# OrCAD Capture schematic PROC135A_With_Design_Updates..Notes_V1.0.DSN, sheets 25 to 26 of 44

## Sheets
25 25. TEST AUTOMATION: size C; title: TEST AUTOMATION
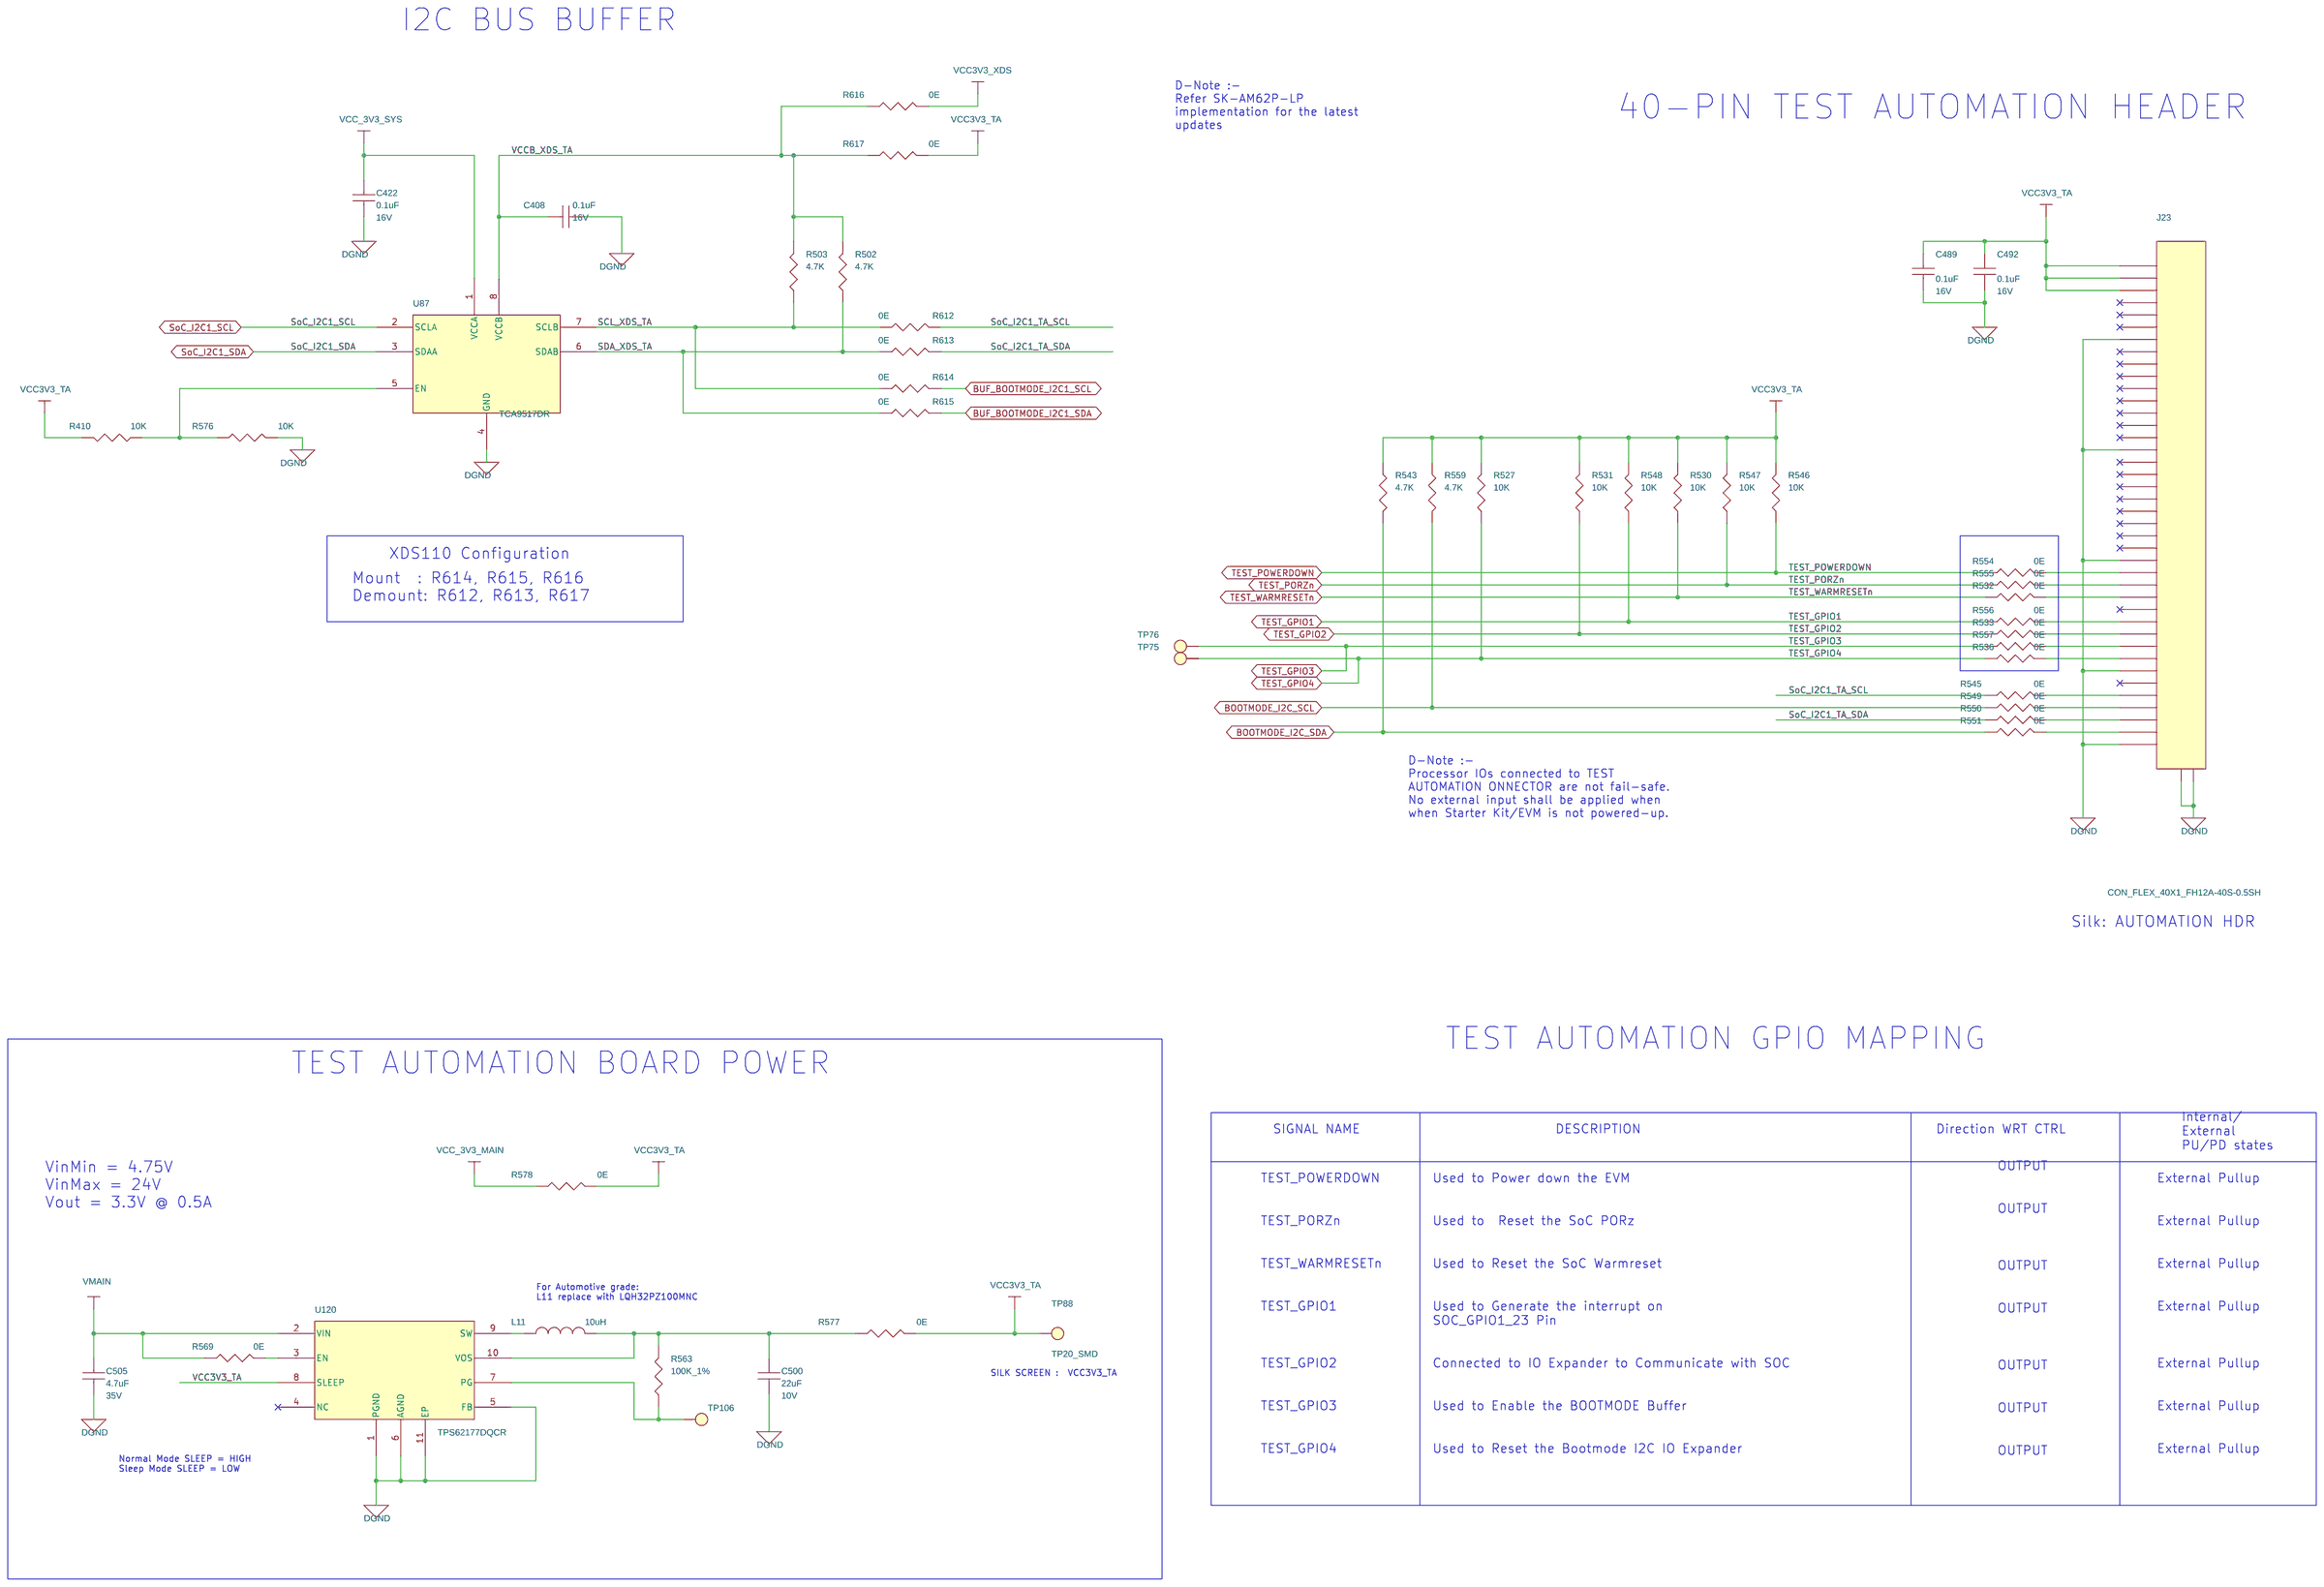
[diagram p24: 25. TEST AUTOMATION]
26 26. BOOT MODE BUFFER & SWITCHES: size C; title: BOOT MODE BUFFER & SWITCHES
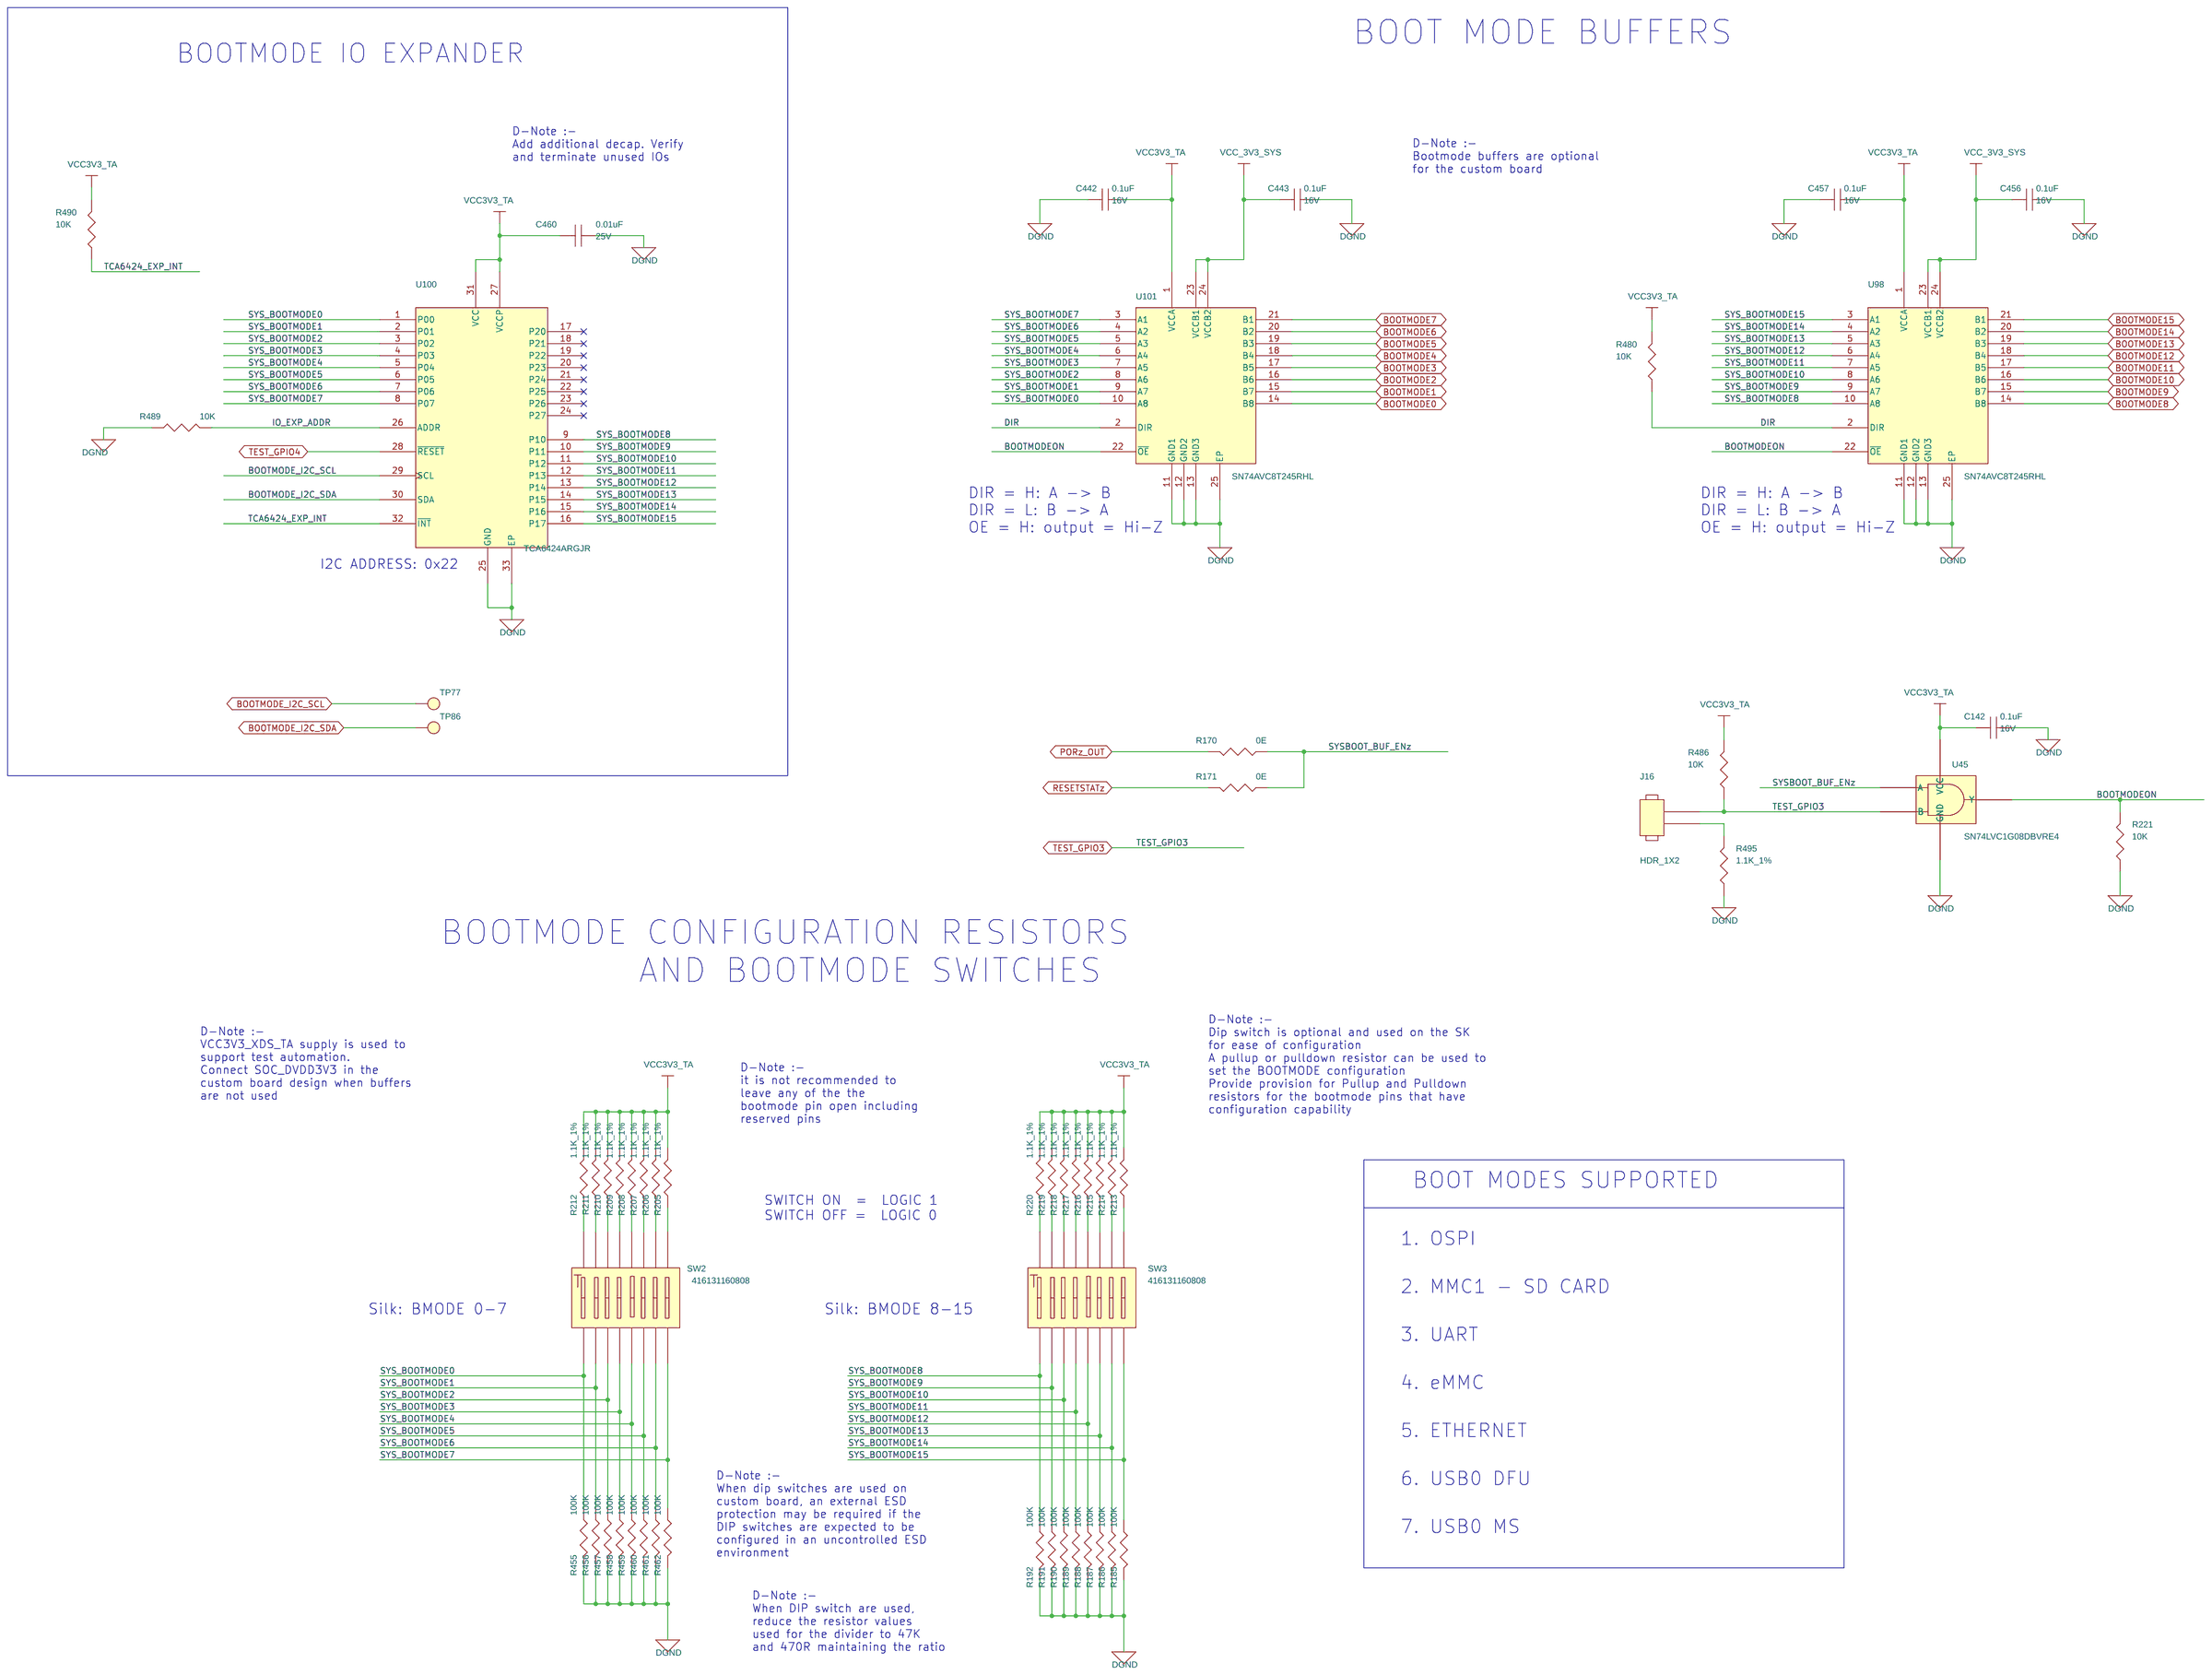
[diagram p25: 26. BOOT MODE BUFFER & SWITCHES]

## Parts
sheet 25. TEST AUTOMATION
C408  0.1uF  [CAP0201_0-5]
C422  0.1uF  [CAP0201_0-5]
C489  0.1uF  [CAP0201_0-5]
C492  0.1uF  [CAP0201_0-5]
C500  22uF  [CAP0603_1]
C505  4.7uF  [CAP0603_1]
J23  CON_FLEX_40X1_FH12A-40S-0.5SH  [CON_FLEX40X1_FH12A_S_R_S]
L11  10uH  [IND_1277AS-H_130X110_SMD_1-2]
R410  10K  [RES0201_0-5]
R502  4.7K  [RES0201_0-5]
R503  4.7K  [RES0201_0-5]
R527  10K  [RES0201_0-5]
R530  10K  [RES0201_0-5]
R531  10K  [RES0201_0-5]
R532  0E  [RES0201_0-5]
R533  0E  [RES0201_0-5]
R536  0E  [RES0201_0-5]
R543  4.7K  [RES0201_0-5]
R545  0E  [RES0201_0-5]
R546  10K  [RES0201_0-5]
R547  10K  [RES0201_0-5]
R548  10K  [RES0201_0-5]
R549  0E  [RES0201_0-5]
R550  0E  [RES0201_0-5]
R551  0E  [RES0201_0-5]
R554  0E  [RES0201_0-5]
R555  0E  [RES0201_0-5]
R556  0E  [RES0201_0-5]
R557  0E  [RES0201_0-5]
R559  4.7K  [RES0201_0-5]
R563  100K_1%  [RES0402_0-5]
R569  0E  [RES0402_0-5]
R576  10K  [RES0201_0-5]
R577  0E  [RES0805_0-75]
R578  0E  [RES0805_0-75]
R612  0E  [RES0201_0-5]
R613  0E  [RES0201_0-5]
R614  0E  [RES0201_0-5]
R615  0E  [RES0201_0-5]
R616  0E  [RES0402_0-5]
R617  0E  [RES0402_0-5]
TP75  TP20_SMD  [TP20_SMD]
TP76  TP20_SMD  [TP20_SMD]
TP88  TP20_SMD  [TP20_SMD]
TP106  TP20_SMD  [TP20_SMD]
U87  TCA9517DR  [SOIC8_1-8]
U120  TPS62177DQCR  [WSON10_19-68_80X120_0-8]
sheet 26. BOOT MODE BUFFER & SWITCHES
C142  0.1uF  [CAP0201_0-5]
C442  0.1uF  [CAP0201_0-5]
C443  0.1uF  [CAP0201_0-5]
C456  0.1uF  [CAP0201_0-5]
C457  0.1uF  [CAP0201_0-5]
C460  0.01uF  [CAP0201_0-5]
J16  HDR_1X2  [HDR_1X2_90120-0122_S_T_5-6]
R170  0E  [RES0201_0-5]
R171  0E  [RES0201_0-5]
R185  100K  [RES0201_0-5]
R186  100K  [RES0201_0-5]
R187  100K  [RES0201_0-5]
R188  100K  [RES0201_0-5]
R189  100K  [RES0201_0-5]
R190  100K  [RES0201_0-5]
R191  100K  [RES0201_0-5]
R192  100K  [RES0201_0-5]
R205  1.1K_1%  [RES0201_0-5]
R206  1.1K_1%  [RES0201_0-5]
R207  1.1K_1%  [RES0201_0-5]
R208  1.1K_1%  [RES0201_0-5]
R209  1.1K_1%  [RES0201_0-5]
R210  1.1K_1%  [RES0201_0-5]
R211  1.1K_1%  [RES0201_0-5]
R212  1.1K_1%  [RES0201_0-5]
R213  1.1K_1%  [RES0201_0-5]
R214  1.1K_1%  [RES0201_0-5]
R215  1.1K_1%  [RES0201_0-5]
R216  1.1K_1%  [RES0201_0-5]
R217  1.1K_1%  [RES0201_0-5]
R218  1.1K_1%  [RES0201_0-5]
R219  1.1K_1%  [RES0201_0-5]
R220  1.1K_1%  [RES0201_0-5]
R221  10K  [RES0201_0-5]
R455  100K  [RES0201_0-5]
R456  100K  [RES0201_0-5]
R457  100K  [RES0201_0-5]
R458  100K  [RES0201_0-5]
R459  100K  [RES0201_0-5]
R460  100K  [RES0201_0-5]
R461  100K  [RES0201_0-5]
R462  100K  [RES0201_0-5]
R480  10K  [RES0201_0-5]
R486  10K  [RES0201_0-5]
R489  10K  [RES0201_0-5]
R490  10K  [RES0201_0-5]
R495  1.1K_1%  [RES0201_0-5]
SW2  416131160808  [SW16_416131160808_460X230_SMD_2-7]
SW3  416131160808  [SW16_416131160808_460X230_SMD_2-7]
TP77  TP20_SMD  [TP20_SMD]
TP86  TP20_SMD  [TP20_SMD]
U45  SN74LVC1G08DBVRE4  [SOT23-5]
U98  SN74AVC8T245RHL  [QFN24_19-68_220X140_1]
U100  TCA6424ARGJR  [QFN32_19-68_200X200]
U101  SN74AVC8T245RHL  [QFN24_19-68_220X140_1]

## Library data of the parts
C142 C408 C422 C442 C443 C456 C457 C489 C492 = CAP: CAP CERAMIC 0.1uF 16V 10% X5R 0201; Alt_Mfr_name: YAGEO AMERICA; Alt_Mfr_part_number: CC0402KRX5R8BB104; Chkd/date: MANIRAJA/230118; Crtd /date: MANIRAJA/230118; Custom_Duty: 15%; Customs_HS_Code: 85322990; Distributor_name: DIGIKEY; Distributor_part_number: 490-14305-1-ND; Footprint Path: Y:\MIS_DATABASE\Library\ALTIUM_TOOL\PCB_FOOTPRINTS\Altium_Footprint_Lib.PcbLib; Height: 0.33MM; Library Path: Y:\MIS_DATABASE\Library\ALTIUM_TOOL\SCHEMATICS_PARTS\MS_DISCRETE_Library.schlib; Mfr_name: MURATA; Mfr_part_number: GRM033R61C104KE14D; Mistral Part No: 120009030072-R; Package: 0201; Part_type: CAPACITORS\CERAMIC; Project: TI_MAXIE_CPB; RoHS: RoHS; Temperature: -55°C+85°C; Tolerance: 10%; Voltage: 16V; Wattage: NA; Weight: 0.33mg; Datasheet: Y:\MIS_DATABASE\DATASHEETS\CAPACITORS\GRM033R61C104KE14.PDF
C500 = CAP: CAP CERAMIC 22uF 10V 20% X5R 0603; Chkd/date: MANIRAJA/230118; Crtd /date: MANIRAJA/230118; Custom_Duty: 15%; Customs_HS_Code: 85322990; Distributor_name: DIGIKEY; Distributor_part_number: 490-10476-1-ND; Footprint Path: Y:\MIS_DATABASE\Library\ALTIUM_TOOL\PCB_FOOTPRINTS\Altium_Footprint_Lib.PcbLib; Height: 1.00MM; Library Path: Y:\MIS_DATABASE\Library\ALTIUM_TOOL\SCHEMATICS_PARTS\MS_DISCRETE_Library.schlib; Mfr_name: MURATA; Mfr_part_number: GRM188R61A226ME15D; Mistral Part No: 120014100009-R; Package: 0603; Part_type: CAPACITORS\CERAMIC; Project: TI_MAXIE_CPB; RoHS: RoHS; Temperature: -55°C+85°C; Tolerance: 20%; Voltage: 10V; Wattage: NA; Weight: 6.3mg; Datasheet: Y:\MIS_DATABASE\DATASHEETS\CAPACITORS\GRM188R61A226ME15.PDF
C505 = CAP: CAP CERAMIC 4.7uF 35V 20% X5R 0603; Chkd/date: MANIRAJA/120520; Crtd /date: ALVY/120520; Custom_Duty: 15%; Customs_HS_Code: 85322990; Distributor_name: DIGIKEY; Distributor_part_number: 490-11995-1-ND; Footprint Path: Y:\MIS_DATABASE\Library\ALTIUM_TOOL\PCB_FOOTPRINTS\Altium_Footprint_Lib.PcbLib; Height: 1.00MM; Library Path: Y:\MIS_DATABASE\Library\ALTIUM_TOOL\SCHEMATICS_PARTS\MS_DISCRETE_Library.schlib; Mfr_name: MURATA; Mfr_part_number: GRM188R6YA475ME15D; Mistral Part No: 120020050017-R; Package: 0603; Part_type: CAPACITORS\CERAMIC; Project: SD865_NANOSOM; RoHS: RoHS; Temperature: -55°C+85°C; Tolerance: 20%; Voltage: 35V; Wattage: NA; Weight: 6.3mg; Datasheet: Y:\MIS_DATABASE\DATASHEETS\CAPACITORS\GRM188R6YA475ME15.PDF
J23 = CON_FLEX_40X1_FH12A-40S-0.5SH: CON FPC 40X1 0.50MM PITCH RT TOP SMD; Chkd/date: SHREESHAIL/201106; Crtd /date: MAZHAR/171106; Custom_Duty: 24%; Customs_HS_Code: 85369090; Distributor_name: DIGIKEY; Distributor_part_number: HFK40CT-ND; Height: 2.00MM; Mfr_name: HIROSE ELECTRIC EUROPE; Mfr_part_number: FH12A-40S-0.5SH(55); Mistral Part No: 150009030176-R; Package: SMD; Part_type: CONNECTOR\FPC; Project: PMP LCD BOARD; Datasheet: Y:\MIS_DATABASE\DATASHEETS\CONNECTORS\FH12SERIES.PDF
L11 = INDUCTOR: IND POWER 10uH 900mA 20% SMD; Chkd/date: MANIRAJA/200921; Crtd /date: ALVY/200921; Custom_Duty: 24%; Customs_HS_Code: 85369090; Distributor_name: DIGIKEY; Distributor_part_number: 490-10589-1-ND; Footprint Path: Y:\MIS_DATABASE\Library\ALTIUM_TOOL\PCB_FOOTPRINTS\Altium_Footprint_Lib.PcbLib; Height: 1.20MM; Library Path: Y:\MIS_DATABASE\Library\ALTIUM_TOOL\SCHEMATICS_PARTS\MS_DISCRETE_Library.schlib; Mfr_name: MURATA; Mfr_part_number: 1277AS-H-100M=P2; Mistral Part No: 130021090022-R; Package: SMD; Project: TI_AM62x SKEVM_BRD; RoHS: RoHS; Temperature: -40°C+85°C; Tolerance: 20%; Voltage: NA; Wattage: NA; Weight: NA; Datasheet: Y:\MIS_DATABASE\DATASHEETS\DISCRETES\INDUCTORS\MURATA-1277AS-H.PDF
R221 R410 R480 R486 R489 R490 R527 R530 R531 R546-R548 R576 = RESISTOR: RES 10K 1/20W 5% 0201; Chkd/date: MANIRAJA/050517; Crtd /date: MANIRAJA/050517; Custom_Duty: 15%; Customs_HS_Code: 85332119; Distributor_name: DIGIKEY; Distributor_part_number: 311-10KNCT-ND; Footprint Path: Y:\MIS_DATABASE\Library\ALTIUM_TOOL\PCB_FOOTPRINTS\Altium_Footprint_Lib.PcbLib; Height: 0.26MM; Library Path: Y:\MIS_DATABASE\Library\ALTIUM_TOOL\SCHEMATICS_PARTS\MS_DISCRETE_Library.schlib; Mfr_name: YAGEO AMERICA; Mfr_part_number: RC0201JR-0710KL; Mistral Part No: 110010070051-R; Package: 0201; Part_type: RESISTORS\FIXED; Project: GOLDEN-I LITE; RoHS: RoHS; Temperature: -55°C+125°C; Tolerance: 5%; Voltage: NA; Wattage: 1/20W; Weight: 0.17mg; Datasheet: Y:\MIS_DATABASE\DATASHEETS\RESISTORS\RCXXXXL-SER_MAR18.PDF
R502 R503 R543 R559 = RESISTOR: RES 4.7K 1/20W 5% 0201; Chkd/date: MANIRAJA/200921; Crtd /date: ALVY/200921; Custom_Duty: 15%; Customs_HS_Code: 85332119; Distributor_name: DIGIKEY; Distributor_part_number: 311-4.7KNCT-ND; Footprint Path: Y:\MIS_DATABASE\Library\ALTIUM_TOOL\PCB_FOOTPRINTS\Altium_Footprint_Lib.PcbLib; Height: 0.26MM; Library Path: Y:\MIS_DATABASE\Library\ALTIUM_TOOL\SCHEMATICS_PARTS\MS_DISCRETE_Library.schlib; Mfr_name: YAGEO AMERICA; Mfr_part_number: RC0201JR-074K7L; Mistral Part No: 110021090007-R; Package: 0201; Part_type: RESISTORS\FIXED; Project: TI_AM62x SKEVM_BRD; RoHS: RoHS; Temperature: -55°C+125°C; Tolerance: 5%; Voltage: NA; Wattage: 1/20W; Weight: 0.17mg; Datasheet: Y:\MIS_DATABASE\DATASHEETS\RESISTORS\RCXXXXL-SER_MAR18.PDF
R170 R171 R532 R533 R536 R545 R549-R551 R554-R557 R612-R615 = RESISTOR: RES 0E 1/20W 5% 0201; Chkd/date: NAVEED/301214; Crtd /date: MUDDU/120710; Custom_Duty: 15%; Customs_HS_Code: 85332119; Distributor_name: DIGIKEY; Distributor_part_number: 311-0.0NCT-ND; Footprint Path: Y:\MIS_DATABASE\Library\ALTIUM_TOOL\PCB_FOOTPRINTS\Altium_Footprint_Lib.PcbLib; Height: 0.26MM; Library Path: Y:\MIS_DATABASE\Library\ALTIUM_TOOL\SCHEMATICS_PARTS\MS_DISCRETE_Library.schlib; Mfr_name: YAGEO AMERICA; Mfr_part_number: RC0201JR-070RL; Mistral Part No: 110010070067-R; Package: 0201; Part_type: RESISTORS\FIXED; Project: PB_BUGBASE; RoHS: RoHS; Temperature: -55°C+125°C; Tolerance: 5%; Voltage: NA; Wattage: 1/20W; Weight: 0.17mg; Datasheet: Y:\MIS_DATABASE\DATASHEETS\RESISTORS\RCXXXXL-SER_MAR18.PDF
R563 = RESISTOR: RES 100K 1/10W 1% 0402; Chkd/date: VASANTHA/201216; Crtd /date: MAZHAR/130306; Custom_Duty: 15%; Customs_HS_Code: 85332119; Distributor_name: DIGIKEY; Distributor_part_number: P100KLCT-ND; Footprint Path: Y:\MIS_DATABASE\Library\ALTIUM_TOOL\PCB_FOOTPRINTS\Altium_Footprint_Lib.PcbLib; Height: 0.40MM; Library Path: Y:\MIS_DATABASE\Library\ALTIUM_TOOL\SCHEMATICS_PARTS\MS_DISCRETE_Library.schlib; Mfr_name: PANASONIC-ECG; Mfr_part_number: ERJ-2RKF1003X; Mistral Part No: 110009030187-R; Package: 0402; Part_type: RESISTORS\FIXED; Project: J32; RoHS: RoHS; Temperature: -55°C+155°C; Tolerance: 1%; Voltage: NA; Wattage: 1/10W; Weight: 0.8mg; Datasheet: Y:\MIS_DATABASE\DATASHEETS\RESISTORS\PAN-ERJSER_NOV17.PDF
R569 = RESISTOR: RES 0E 1/16W JUMPER 0402; Chkd/date: VASANTHA/201216; Crtd /date: MUDDU/190810; Custom_Duty: 15%; Customs_HS_Code: 85332119; Distributor_name: DIGIKEY; Distributor_part_number: 541-0.0JCT-ND; Footprint Path: Y:\MIS_DATABASE\Library\ALTIUM_TOOL\PCB_FOOTPRINTS\Altium_Footprint_Lib.PcbLib; Height: 0.40MM; Library Path: Y:\MIS_DATABASE\Library\ALTIUM_TOOL\SCHEMATICS_PARTS\MS_DISCRETE_Library.schlib; Mfr_name: VISHAY; Mfr_part_number: CRCW04020000Z0ED; Mistral Part No: 110010080019-R; Package: 0402; Part_type: RESISTORS\FIXED; Project: PB_BUGBASE; RoHS: RoHS; Temperature: -55°C+155°C; Tolerance: NA; Voltage: NA; Wattage: 1/16W; Weight: 0.65mg; Datasheet: Y:\MIS_DATABASE\DATASHEETS\RESISTORS\CRCW0603.PDF
R577 R578 = RESISTOR: RES 0E 1/8W 5% 0805; Chkd/date: VASANTHA/130416; Crtd /date: JEBRAN/020316; Custom_Duty: 15%; Customs_HS_Code: 85332119; Distributor_name: DIGIKEY; Distributor_part_number: 311-0.0ARCT-ND; Footprint Path: Y:\MIS_DATABASE\Library\ALTIUM_TOOL\PCB_FOOTPRINTS\Altium_Footprint_Lib.PcbLib; Height: 0.60MM; Library Path: Y:\MIS_DATABASE\Library\ALTIUM_TOOL\SCHEMATICS_PARTS\MS_DISCRETE_Library.schlib; Mfr_name: YAGEO AMERICA; Mfr_part_number: RC0805JR-070RL; Mistral Part No: 110009030074-R; Package: 0805; Part_type: RESISTORS\FIXED; Project: ZK_BIOMETRIC; RoHS: RoHS; Temperature: -55°C+155°C; Tolerance: 5%; Voltage: NA; Wattage: 1/8W; Weight: 5.5mg; Datasheet: Y:\MIS_DATABASE\DATASHEETS\RESISTORS\RCXXXXL-SER_MAR18.PDF
R616 R617 = RESISTOR: RES 0E 1/10W JUMPER 0402; Chkd/date: VASANTHA/061216; Crtd /date: NAVEED/201014; Custom_Duty: 15%; Customs_HS_Code: 85332119; Distributor_name: DIGIKEY; Distributor_part_number: P0.0JCT-ND; Footprint Path: Y:\MIS_DATABASE\Library\ALTIUM_TOOL\PCB_FOOTPRINTS\Altium_Footprint_Lib.PcbLib; Height: 0.40MM; IBISSP_MODLES: VALUE REPEATING 2 TIME; Library Path: Y:\MIS_DATABASE\Library\ALTIUM_TOOL\SCHEMATICS_PARTS\MS_DISCRETE_Library.schlib; Mfr_name: PANASONIC-ECG; Mfr_part_number: ERJ-2GE0R00X; Mistral Part No: 110018030052-R; Package: 0402; Part_type: RESISTORS\FIXED; Project: AEGIS POM; RoHS: RoHS; Temperature: -55°C+155°C; Tolerance: NA; Voltage: NA; Wattage: 1/10W; Weight: 0.8mg; Datasheet: Y:\MIS_DATABASE\DATASHEETS\RESISTORS\PAN-ERJSER_NOV17.PDF
TP75-TP77 TP86 TP106 = TESTPOINT: TESTPOINT CIR 20 SMD; Chkd/date: SHREESHAIL/171006; Crtd /date: MAZHAR/171006; Custom_Duty: NA; Customs_HS_Code: NA; Distributor_name: NA; Distributor_part_number: NA; Footprint Path: Y:\MIS_DATABASE\Library\ALTIUM_TOOL\PCB_FOOTPRINTS\Altium_Footprint_Lib.PcbLib; Height: NA; Library Path: Y:\MIS_DATABASE\Library\ALTIUM_TOOL\SCHEMATICS_PARTS\MS_DISCRETE_Library.schlib; MECHANICAL 3D STEP FILE: NA; Mfr_name: LOCAL; Mistral Part No: NA; Package: SMD; Project: BT MODULE_CSRBC04; RoHS: NA; Temperature: NA; Tolerance: NA; Voltage: NA; Wattage: NA; Weight: NA; Datasheet: NA
TP88 = TESTPOINT: TESTPOINT CIR 20 SMD; Chkd/date: SHREESHAIL/171006; Crtd /date: MAZHAR/171006; Custom_Duty: NA; Customs_HS_Code: NA; Distributor_name: NA; Distributor_part_number: NA; Footprint Path: Y:\MIS_DATABASE\Library\ALTIUM_TOOL\PCB_FOOTPRINTS\Altium_Footprint_Lib.PcbLib; Height: NA; Library Path: Y:\MIS_DATABASE\Library\ALTIUM_TOOL\SCHEMATICS_PARTS\MS_DISCRETE_Library.schlib; MECHANICAL 3D STEP FILE: NA; Manufacturer: LOCAL; Mfr_name: LOCAL; Mistral Part No: NA; Package: SMD; Project: BT MODULE_CSRBC04; RoHS: NA; Temperature: NA; Tolerance: NA; Voltage: NA; Wattage: NA; Weight: NA; Datasheet: NA
U87 = TCA9517DGKR_VSSOP8: IC 2-CHANNEL BI-DIR LEVEL-SHIFTING I2C BUS REPEATER SOIC8; Chkd/date: MANIRAJA/171121; Crtd /date: ALVY/161121; Custom_Duty: 15%; Customs_HS_Code: 85423100; Distributor_name: DIGIKEY; Distributor_part_number: 296-39221-1-ND; Footprint Path: Y:\MIS_DATABASE\Library\ALTIUM_TOOL\PCB_FOOTPRINTS\Altium_Footprint_Lib.PcbLib; Height: 1.75MM; Library Path: Y:\MIS_DATABASE\Library\ALTIUM_TOOL\SCHEMATICS_PARTS\MS_MISCINTERFACE_Library.schlib; Mfr_name: TEXAS INSTRUMENTS; Mistral Part No: 141021110017-R; Package: SOIC8; Part_type: ICS\INTERFACE\LEVEL TRANSLATOR; Project: EXCITER MULTI-CH RX UNIT; RoHS: RoHS; Temperature: -40°C+85°C; Tolerance: NA; Voltage: NA; Wattage: NA; Weight: 540mg; Datasheet: Y:\MIS_DATABASE\DATASHEETS\ICS\INTERFACE\TCA9517.PDF
U120 = TPS62177_WSON10: IC 3.3V 0.5A STEP DOWN CONVERTER WITH SLEEP MODE WSON10; Chkd/date: MANIRAJA/170719; Crtd /date: MANIRAJA/170719; Custom_Duty: 15%; Customs_HS_Code: 85423100; Distributor_name: DIGIKEY; Distributor_part_number: 296-41856-1-ND; Footprint Path: Y:\MIS_DATABASE\Library\ALTIUM_TOOL\PCB_FOOTPRINTS\Altium_Footprint_Lib.PcbLib; Height: 0.80MM; Library Path: Y:\MIS_DATABASE\Library\ALTIUM_TOOL\SCHEMATICS_PARTS\MS_MISCPOWER_Library.schlib; Mfr_name: TEXAS INSTRUMENTS; Mistral Part No: 142019070007-R; Package: WSON10; Part_type: ICS\POWER\DC-DC CONVERTER; Project: TI_MAXIE_CPB; RoHS: RoHS; Temperature: -40°C+85°C; Tolerance: NA; Voltage: NA; Wattage: NA; Weight: 15mg; Datasheet: Y:\MIS_DATABASE\DATASHEETS\ICS\POWER\TPS62177.PDF
C460 = CAP: CAP CERAMIC 0.01uF 25V 10% X5R 0201; Chkd/date: MANIRAJA/230118; Crtd /date: MANIRAJA/230118; Custom_Duty: 15%; Customs_HS_Code: 85322990; Distributor_name: DIGIKEY; Distributor_part_number: GRM033R61E103KA12J-ND; Footprint Path: Y:\MIS_DATABASE\Library\ALTIUM_TOOL\PCB_FOOTPRINTS\Altium_Footprint_Lib.PcbLib; Height: 0.33MM; Library Path: Y:\MIS_DATABASE\Library\ALTIUM_TOOL\SCHEMATICS_PARTS\MS_DISCRETE_Library.schlib; Mfr_name: MURATA; Mfr_part_number: GRM033R61E103KA12J; Mistral Part No: 120018010007-R; Package: 0201; Part_type: CAPACITORS\CERAMIC; Project: TI_MAXIE_CPB; RoHS: RoHS; Temperature: -55°C+85°C; Tolerance: 10%; Voltage: 25V; Wattage: NA; Weight: 0.33mg; Datasheet: Y:\MIS_DATABASE\DATASHEETS\CAPACITORS\GRM033R61E103KA12.PDF
J16 = HEADER_2X1: CON HDR 1X2 2.54MM PITCH ST TH; Chkd/date: NAVEED/210714; Crtd /date: USMAN/031012; Custom_Duty: 24%; Customs_HS_Code: 85369090; Distributor_name: DIGIKEY; Distributor_part_number: WM8072-ND; Footprint Path: Y:\MIS_DATABASE\Library\ALTIUM_TOOL\PCB_FOOTPRINTS\Altium_Footprint_Lib.PcbLib; Height: 5.60MM; Library Path: Y:\MIS_DATABASE\Library\ALTIUM_TOOL\SCHEMATICS_PARTS\MS_CONNECTOR_Library.schlib; Mfr_name: MOLEX; Mfr_part_number: 90120-0122; Mistral Part No: 150012100005-R; Package: THRU-HOLE; Part_type: CONNECTOR\HEADERS; Project: NPOL_FEP; RoHS: RoHS; Temperature: -55°C+125°C; Tolerance: NA; Voltage: NA; Wattage: NA; Weight: 122mg; Datasheet: Y:\MIS_DATABASE\DATASHEETS\CONNECTORS\90120-XX.PDF
R185-R192 R455-R462 = RESISTOR: RES 100K 1/20W 5% 0201; Chkd/date: MANIRAJA/050517; Crtd /date: MANIRAJA/050517; Custom_Duty: 15%; Customs_HS_Code: 85332119; Distributor_name: DIGIKEY; Distributor_part_number: 311-100KNCT-ND; Footprint Path: Y:\MIS_DATABASE\Library\ALTIUM_TOOL\PCB_FOOTPRINTS\Altium_Footprint_Lib.PcbLib; Height: 0.26MM; Library Path: Y:\MIS_DATABASE\Library\ALTIUM_TOOL\SCHEMATICS_PARTS\MS_DISCRETE_Library.schlib; Mfr_name: YAGEO AMERICA; Mfr_part_number: RC0201JR-07100KL; Mistral Part No: 110009030176-R; Package: 0201; Part_type: RESISTORS\FIXED; Project: GOLDEN-I LITE; RoHS: RoHS; Temperature: -55°C+125°C; Tolerance: 5%; Voltage: NA; Wattage: 1/20W; Weight: 0.17mg; Datasheet: Y:\MIS_DATABASE\DATASHEETS\RESISTORS\RCXXXXL-SER_MAR18.PDF
R205-R220 R495 = RESISTOR: RES 1.1K 1/20W 1% 0201; Chkd/date: MANIRAJA/270721; Crtd /date: ALVY/260721; Custom_Duty: 15%; Customs_HS_Code: 85332119; Distributor_name: DIGIKEY; Distributor_part_number: YAG2474CT-ND; Footprint Path: Y:\MIS_DATABASE\Library\ALTIUM_TOOL\PCB_FOOTPRINTS\Altium_Footprint_Lib.PcbLib; Height: 0.26MM; Library Path: Y:\MIS_DATABASE\Library\ALTIUM_TOOL\SCHEMATICS_PARTS\MS_DISCRETE_Library.schlib; Mfr_name: YAGEO AMERICA; Mfr_part_number: RC0201FR-071K1L; Mistral Part No: 110009030097-R; Package: 0201; Part_type: RESISTORS\FIXED; Project: TI_AM335x SK_BRD; RoHS: RoHS; Temperature: -55°C+125°C; Tolerance: 1%; Voltage: NA; Wattage: 1/20W; Weight: 0.17mg; Datasheet: Y:\MIS_DATABASE\DATASHEETS\RESISTORS\RCXXXXL-SER_MAR18.PDF
SW2 SW3 = SW16_CHS-08A: SWITCH SLIDE SPST ST SMD; Chkd/date: MANIRAJA/051020; Crtd /date: ALVY/011020; Custom_Duty: 24%; Customs_HS_Code: 85369090; Distributor_name: DIGIKEY; Distributor_part_number: 732-3857-1-ND; Footprint Path: Y:\MIS_DATABASE\Library\ALTIUM_TOOL\PCB_FOOTPRINTS\Altium_Footprint_Lib.PcbLib; Height: 2.65MM; Library Path: Y:\MIS_DATABASE\Library\ALTIUM_TOOL\SCHEMATICS_PARTS\MS_SWITCH_Library.schlib; Mfr_name: WURTH ELECTRONICS; Mistral Part No: 130020100001-R; Package: SMD; Part_type: ELECTRO-MECHANICAL\SWITCH; Project: AM64X_SKEVM; RoHS: RoHS; Temperature: -40°C+85°C; Tolerance: NA; Voltage: NA; Wattage: NA; Weight: 281.7mg; Datasheet: Y:\MIS_DATABASE\DATASHEETS\MISC\SWITCHES\4161311608XX.PDF
U45 = SN74LVC1G08DBVRE4_SOT23-5: IC SINGLE 2-INPUT POSITIVE AND GATE SOT23-5; Chkd/date: SUHAS/221010; Crtd /date: USMAN/151008; Custom_Duty: 15%; Customs_HS_Code: 85423100; Distributor_name: DIGIKEY; Distributor_part_number: SN74LVC1G08DBVRE4-ND; Height: 1.45MM; Mfr_name: TEXAS INSTRUMENTS; Mistral Part No: 141009060026-R; Part_type: ICS\DIGITAL\GATES; Project: KHAN_MAIN; RoHS: Sb/ Br FREE; Temperature: -40°C+85°C; Datasheet: Y:\MIS_DATABASE\DATASHEETS\ICS\DIGITAL\GATES\SN74LVC1G08.PDF
U98 U101 = SN74AVC8T245RHL_QFN24: IC BUS TRANSCEIVER 8-BIT DUAL-SUPPLY QFN24; Chkd/date: VASANTHA/231216; Crtd /date: BAVISH/290411; Custom_Duty: 15%; Customs_HS_Code: 85423100; Distributor_name: DIGIKEY; Distributor_part_number: 296-17859-1-ND; Height: 1.00MM; Mfr_name: TEXAS INSTRUMENTS; Mfr_part_number: SN74AVC8T245RHLR; Mistral Part No: 143011040001-R; Package: QFN24; Part_type: ICS\TELECOM\TRANSCEIVER; Project: OMAPL1_PEC20; RoHS: RoHS; Temperature: -40°C+85°C; Tolerance: NA; Voltage: NA; Wattage: NA; Weight: NA; Datasheet: Y:\MIS_DATABASE\DATASHEETS\ICS\DIGITAL\BUSTRANSCEIVER\SN74AVC8T245.PDF
U100 = TCA6424ARGJR_QFN32: IC I2C I/O EXPANDER 24B UQFN32; Chkd/date: NAVEED/100715; Crtd /date: NAVEED/100914; Custom_Duty: 15%; Customs_HS_Code: 85423100; Distributor_name: DIGIKEY; Distributor_part_number: 296-27844-1-ND; Height: 0.60MM; Mfr_name: TEXAS INSTRUMENTS; Mistral Part No: 141014090009-R; Package: UQFN32; Part_type: ICS\DIGITAL\BUSTRANSCEIVER; Project: ZK_BIOMETRIC; RoHS: RoHS; Temperature: -40°C+85°C; Weight: NA; Datasheet: Y:\MIS_DATABASE\DATASHEETS\ICS\DIGITAL\BUSTRANSCEIVER\TCA6424AR.PDF

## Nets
DGND: C142.2 C408.2 C422.2 C442.1 C443.2 C456.2 C457.1 C460.1 C489.2 C492.2 C500.2 C505.2 J23.7 J23.16 J23.25 J23.34 J23.40 J23.41 J23.42 R185.2 R186.2 R187.2 R188.2 R189.2 R190.2 R191.2 R192.2 R221.1 R455.2 R456.2 R457.2 R458.2 R459.2 R460.2 R461.2 R462.2 R489.2 R495.1 R576.1 U45.3(GND) U87.4(GND) U98.11(GND1) U98.12(GND2) U98.13(GND3) U98.25(EP) U100.25(GND) U100.33(EP) U101.11(GND1) U101.12(GND2) U101.13(GND3) U101.25(EP) U120.1(PGND) U120.5(FB) U120.6(AGND) U120.11(EP) ; also on sheet 9 10 11 12 13 14 15 16 17 18 19 20 21 22 23 24 27 28 29 30 31 32 33 34 35 36 37 38 39 40 41 42 43
VCC3V3_TA: C142.1 C442.2 C457.2 C460.2 C489.1 C492.1 J23.1 J23.2 J23.3 R205.2 R206.2 R207.2 R208.2 R209.2 R210.2 R211.2 R212.2 R213.2 R214.2 R215.2 R216.2 R217.2 R218.2 R219.2 R220.2 R410.1 R480.2 R486.2 R490.2 R527.2 R530.2 R531.2 R543.1 R546.2 R547.2 R548.2 R559.1 R577.2 R578.2 R617.2 TP88.1(TP) U45.5(VCC) U98.1(VCCA) U100.27(VCCP) U100.31(VCC) U101.1(VCCA) U120.8(SLEEP) ; also on sheet 27
VCC3V3_XDS: R616.2 ; also on sheet 27 28
VCC_3V3_MAIN: R578.1 ; also on sheet 11 12 14
VCC_3V3_SYS: C422.1 C443.1 C456.1 U87.1(VCCA) U98.23(VCCB1) U98.24(VCCB2) U101.23(VCCB1) U101.24(VCCB2) ; also on sheet 9 10 12 13 17 18 19 21 22 23 28 29 30 32 33 34 35 36 37 38 39 40 41 42
VCCB_XDS_TA: C408.1 R502.1 R503.1 R616.1 R617.1 U87.8(VCCB)
BOOTMODE0: U101.14(B8) ; also on sheet 31
BOOTMODE1: U101.15(B7) ; also on sheet 31
BOOTMODE2: U101.16(B6) ; also on sheet 31
BOOTMODE3: U101.17(B5) ; also on sheet 31
BOOTMODE4: U101.18(B4) ; also on sheet 31
BOOTMODE5: U101.19(B3) ; also on sheet 31
BOOTMODE6: U101.20(B2) ; also on sheet 31
BOOTMODE7: U101.21(B1) ; also on sheet 31
BOOTMODE8: U98.14(B8) ; also on sheet 31
BOOTMODE9: U98.15(B7) ; also on sheet 31
BOOTMODE10: U98.16(B6) ; also on sheet 31
BOOTMODE11: U98.17(B5) ; also on sheet 31
BOOTMODE12: U98.18(B4) ; also on sheet 31
BOOTMODE13: U98.19(B3) ; also on sheet 31
BOOTMODE14: U98.20(B2) ; also on sheet 31
BOOTMODE15: U98.21(B1) ; also on sheet 31
BOOTMODE_I2C_SCL: R549.1 R559.2 TP77.1(TP) U100.29(SCL) ; also on sheet 27
BOOTMODE_I2C_SDA: R543.2 R551.1 TP86.1(TP) U100.30(SDA) ; also on sheet 27
BOOTMODEON: R221.2 U45.4(Y) U98.22(~{OE}) U101.22(~{OE})
BUF_BOOTMODE_I2C1_SCL: R614.1 ; also on sheet 27
BUF_BOOTMODE_I2C1_SDA: R615.1 ; also on sheet 27
DIR: R480.1 U98.2(DIR) U101.2(DIR)
IO_EXP_ADDR: R489.1 U100.26(ADDR)
PORz_OUT: R170.2 ; also on sheet 19 22 23 41
RESETSTATz: R171.2 ; also on sheet 18 19 20 22 23 37 38 39 40 41
SCL_XDS_TA: R503.2 R612.2 R614.2 U87.7(SCLB)
SDA_XDS_TA: R502.2 R613.2 R615.2 U87.6(SDAB)
SOC_I2C1_SCL: U87.2(SCLA) ; also on sheet 13 21 38 39 40 41
SOC_I2C1_SDA: U87.3(SDAA) ; also on sheet 13 21 38 39 40 41
SoC_I2C1_TA_SCL: R545.1 R612.1
SoC_I2C1_TA_SDA: R550.1 R613.1
SYS_BOOTMODE0: R455.1 SW2.1 U100.1(P00) U101.10(A8)
SYS_BOOTMODE1: R456.1 SW2.2 U100.2(P01) U101.9(A7)
SYS_BOOTMODE2: R457.1 SW2.3 U100.3(P02) U101.8(A6)
SYS_BOOTMODE3: R458.1 SW2.4 U100.4(P03) U101.7(A5)
SYS_BOOTMODE4: R459.1 SW2.5 U100.5(P04) U101.6(A4)
SYS_BOOTMODE5: R460.1 SW2.6 U100.6(P05) U101.5(A3)
SYS_BOOTMODE6: R461.1 SW2.7 U100.7(P06) U101.4(A2)
SYS_BOOTMODE7: R462.1 SW2.8 U100.8(P07) U101.3(A1)
SYS_BOOTMODE8: R192.1 SW3.1 U98.10(A8) U100.9(P10)
SYS_BOOTMODE9: R191.1 SW3.2 U98.9(A7) U100.10(P11)
SYS_BOOTMODE10: R190.1 SW3.3 U98.8(A6) U100.11(P12)
SYS_BOOTMODE11: R189.1 SW3.4 U98.7(A5) U100.12(P13)
SYS_BOOTMODE12: R188.1 SW3.5 U98.6(A4) U100.13(P14)
SYS_BOOTMODE13: R187.1 SW3.6 U98.5(A3) U100.14(P15)
SYS_BOOTMODE14: R186.1 SW3.7 U98.4(A2) U100.15(P16)
SYS_BOOTMODE15: R185.1 SW3.8 U98.3(A1) U100.16(P17)
SYSBOOT_BUF_ENz: R170.1 R171.1 U45.1(A)
TCA6424_EXP_INT: R490.1 U100.32(~{INT})
TEST_GPIO1: R548.1 R556.1 ; also on sheet 27 42
TEST_GPIO2: R531.1 R533.1 ; also on sheet 27 39
TEST_GPIO3: J16.1 R486.1 R557.1 TP76.1(TP) U45.2(B) ; also on sheet 27
TEST_GPIO4: R527.1 R536.1 TP75.1(TP) U100.28(~{RESET}) ; also on sheet 27
TEST_PORZn: R547.1 R555.1 ; also on sheet 27 41
TEST_POWERDOWN: R546.1 R554.1 ; also on sheet 10 12 27
TEST_WARMRESETn: R530.1 R532.1 ; also on sheet 27 42
VMAIN: C505.1 R569.1 U120.2(VIN) ; also on sheet 9 10 11
N16990175: J23.27 R555.2
N16990176: J23.30 R556.2
N16990179: J23.31 R533.2
N16990180: J23.32 R557.2
N16990246: J23.26 R554.2
N16990247: J23.28 R532.2
N16990252: J23.33 R536.2
N17078351: R209.1 SW2.13
N17078353: R210.1 SW2.14
N17078355: R211.1 SW2.15
N17078357: R212.1 SW2.16
N17078758: R215.1 SW3.11
N17078760: R216.1 SW3.12
N17078762: R217.1 SW3.13
N17078764: R218.1 SW3.14
N17078766: R213.1 SW3.9
N17078768: R214.1 SW3.10
N17078770: R219.1 SW3.15
N17078778: R220.1 SW3.16
N17078974: J16.2 R495.2
N17084256: R205.1 SW2.9
N17084257: R206.1 SW2.10
N17084258: R207.1 SW2.11
N17084259: R208.1 SW2.12
N17253632: C500.1 L11.2 R563.2 R577.1 U120.10(VOS)
N17253649: L11.1 U120.9(SW)
N17253673: R563.1 TP106.1(TP) U120.7(PG)
N17253694: R569.2 U120.3(EN)
N18374804: J23.36 R545.2
N18374807: J23.37 R549.2
N18374810: J23.38 R550.2
N18374813: J23.39 R551.2
N23696264: R410.2 R576.2 U87.5(EN)

Not connected (* = marked no-connect by the designer): J23 4* 5* 6* 8* 9* 10* 11* 12* 13* 14* 15* 17* 18* 19* 20* 21* 22* 23* 24* 29* 35*; U100 17(P20)* 18(P21)* 19(P22)* 20(P23)* 21(P24)* 22(P25)* 23(P26)* 24(P27)*; U120 4(NC)*

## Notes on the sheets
sheet 25
- I2C BUS BUFFER
- D-Note :-
  Refer SK-AM62P-LP
  implementation for the latest
  updates
- 40-PIN TEST AUTOMATION HEADER
- XDS110 Configuration
- Mount  : R614, R615, R616
  Demount: R612, R613, R617
- D-Note :-
  Processor IOs connected to TEST
  AUTOMATION ONNECTOR are not fail-safe.
  No external input shall be applied when
  when Starter Kit/EVM is not powered-up.
- Silk: AUTOMATION HDR
- TEST AUTOMATION GPIO MAPPING
- TEST AUTOMATION BOARD POWER
- Internal/
  External
  PU/PD states
- SIGNAL NAME
- DESCRIPTION
- Direction WRT CTRL
- VinMin = 4.75V
  VinMax = 24V
  Vout = 3.3V @ 0.5A
- OUTPUT
  OUTPUT
  OUTPUT
  OUTPUT
  OUTPUT
  OUTPUT
  OUTPUT
- TEST_POWERDOWN
  TEST_PORZn
  TEST_WARMRESETn
  TEST_GPIO1
  TEST_GPIO2
  TEST_GPIO3
  TEST_GPIO4
- Used to Power down the EVM
  Used to  Reset the SoC PORz
  Used to Reset the SoC Warmreset
  Used to Generate the interrupt on
  SOC_GPIO1_23 Pin
  Connected to IO Expander to Communicate with SOC
  Used to Enable the BOOTMODE Buffer
  Used to Reset the Bootmode I2C IO Expander
- External Pullup
  External Pullup
  External Pullup
  External Pullup
  External Pullup
  External Pullup
  External Pullup
- For Automotive grade:
  L11 replace with LQH32PZ100MNC
- SILK SCREEN :  VCC3V3_TA
- Normal Mode SLEEP = HIGH
  Sleep Mode SLEEP = LOW
sheet 26
- BOOT MODE BUFFERS
- BOOTMODE IO EXPANDER
- D-Note :-
  Add additional decap. Verify
  and terminate unused IOs
- D-Note :-
  Bootmode buffers are optional
  for the custom board
- DIR = H: A -> B
  DIR = L: B -> A
  OE = H: output = Hi-Z
- DIR = H: A -> B
  DIR = L: B -> A
  OE = H: output = Hi-Z
- I2C ADDRESS: 0x22
- BOOTMODE CONFIGURATION RESISTORS
             AND BOOTMODE SWITCHES
- D-Note :-
  Dip switch is optional and used on the SK
  for ease of configuration
  A pullup or pulldown resistor can be used to
  set the BOOTMODE configuration
  Provide provision for Pullup and Pulldown
  resistors for the bootmode pins that have
  configuration capability
- D-Note :-
  VCC3V3_XDS_TA supply is used to
  support test automation.
  Connect SOC_DVDD3V3 in the
  custom board design when buffers
  are not used
- D-Note :-
  it is not recommended to
  leave any of the the
  bootmode pin open including
  reserved pins
- BOOT MODES SUPPORTED
- SWITCH ON  =  LOGIC 1
  SWITCH OFF =  LOGIC 0
- 1. OSPI
- 2. MMC1 - SD CARD
- Silk: BMODE 0-7
- Silk: BMODE 8-15
- 3. UART
- 4. eMMC
- 5. ETHERNET
- D-Note :-
  When dip switches are used on
  custom board, an external ESD
  protection may be required if the
  DIP switches are expected to be
  configured in an uncontrolled ESD
  environment
- 6. USB0 DFU
- 7. USB0 MS
- D-Note :-
  When DIP switch are used,
  reduce the resistor values
  used for the divider to 47K
  and 470R maintaining the ratio
